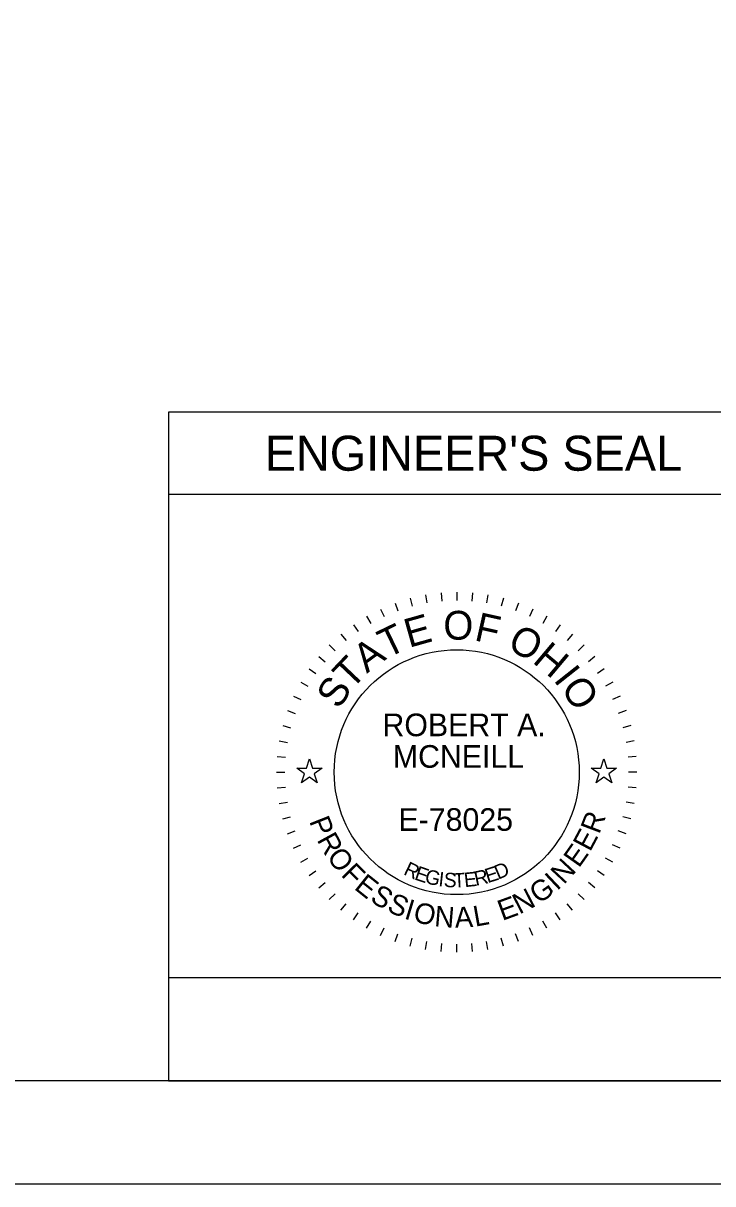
# Model space of a CAD drawing. Extents: x 0 to 34, y 0 to 22.
# Drawn here: x 6.64 to 9.99, y 0 to 5.64 of the extents above; entities that cross this region are included whole.
import ezdxf

# ---------------------------------------------------------------- set-up
doc = ezdxf.new("R2010")
doc.units = 0
for name, color, linetype in [('Default', 7, 'Continuous'), ('SH_Border', 7, 'Continuous'), ('SH_Cut_Line', 7, 'Continuous'), ('SH_Data', 7, 'Continuous')]:
    doc.layers.add(name, color=color, linetype=linetype)

msp = doc.modelspace()

# ---------------------------------------------------------------- linework, layer by layer
at = {"layer": 'Default'}
for points in [[(7.9736, 2.02), (8.0205, 2.02), (8.035, 2.0645), (8.0495, 2.02), (8.0964, 2.02), (8.0585, 1.9924), (8.073, 1.9478), (8.035, 1.9754), (7.997, 1.9478), (8.0115, 1.9924)], [(9.4036, 2.02), (9.4505, 2.02), (9.465, 2.0645), (9.4795, 2.02), (9.5264, 2.02), (9.4885, 1.9924), (9.503, 1.9478), (9.465, 1.9754), (9.427, 1.9478), (9.4415, 1.9924)]]:
    msp.add_lwpolyline(points, close=True, dxfattribs=at)
at = {"layer": 'SH_Border'}
msp.add_lwpolyline([(1.5, 21.5), (33.5, 21.5), (33.5, 0.5), (1.5, 0.5)], close=True, dxfattribs=at)
at = {"layer": 'SH_Cut_Line'}
msp.add_lwpolyline([(0, 0), (34, 0), (34, 22), (0, 22)], close=True, dxfattribs=at)
at = {"layer": 'SH_Data'}
for p, q in [((10.15, 3.75), (7.35, 3.75)), ((7.35, 3.75), (7.35, 0.5)), ((10.15, 3.35), (7.35, 3.35)), ((8.4507, 2.8222), (8.4644, 2.7846)), ((8.5235, 2.8452), (8.5339, 2.8065)), ((8.5981, 2.8617), (8.605, 2.8223)), ((8.6737, 2.8717), (8.6772, 2.8318)), ((8.75, 2.875), (8.75, 2.835)), ((8.8263, 2.8717), (8.8228, 2.8318)), ((8.9019, 2.8617), (8.895, 2.8223)), ((8.9765, 2.8452), (8.9661, 2.8065)), ((9.0493, 2.8222), (9.0356, 2.7846)), ((8.3802, 2.793), (8.3971, 2.7568)), ((9.1198, 2.793), (9.1029, 2.7568)), ((8.2481, 2.7168), (8.2711, 2.684)), ((8.3125, 2.7578), (8.3325, 2.7231)), ((9.1875, 2.7578), (9.1675, 2.7231)), ((9.2519, 2.7168), (9.2289, 2.684)), ((8.1876, 2.6703), (8.2133, 2.6396)), ((9.3124, 2.6703), (9.2867, 2.6396)), ((8.1313, 2.6187), (8.1596, 2.5904)), ((9.3687, 2.6187), (9.3404, 2.5904)), ((8.0797, 2.5624), (8.1104, 2.5367)), ((9.4203, 2.5624), (9.3896, 2.5367)), ((8.0332, 2.5019), (8.066, 2.4789)), ((9.4668, 2.5019), (9.434, 2.4789)), ((7.9922, 2.4375), (8.0269, 2.4175)), ((9.5078, 2.4375), (9.4731, 2.4175)), ((7.957, 2.3698), (7.9932, 2.3529)), ((9.543, 2.3698), (9.5068, 2.3529)), ((7.9278, 2.2993), (7.9654, 2.2856)), ((9.5722, 2.2993), (9.5346, 2.2856)), ((7.9048, 2.2265), (7.9435, 2.2161)), ((9.5952, 2.2265), (9.5565, 2.2161)), ((7.8883, 2.1519), (7.9277, 2.145)), ((9.6117, 2.1519), (9.5723, 2.145)), ((7.8783, 2.0763), (7.9182, 2.0728)), ((9.6217, 2.0763), (9.5818, 2.0728)), ((7.875, 2), (7.915, 2)), ((9.625, 2), (9.585, 2)), ((7.8783, 1.9237), (7.9182, 1.9272)), ((9.6217, 1.9237), (9.5818, 1.9272)), ((7.8883, 1.8481), (7.9277, 1.855)), ((9.6117, 1.8481), (9.5723, 1.855)), ((7.9048, 1.7735), (7.9435, 1.7839)), ((9.5952, 1.7735), (9.5565, 1.7839)), ((7.9278, 1.7007), (7.9654, 1.7144)), ((9.5722, 1.7007), (9.5346, 1.7144)), ((7.957, 1.6302), (7.9932, 1.6471)), ((9.543, 1.6302), (9.5068, 1.6471)), ((7.9922, 1.5625), (8.0269, 1.5825)), ((9.5078, 1.5625), (9.4731, 1.5825)), ((8.0332, 1.4981), (8.066, 1.5211)), ((9.4668, 1.4981), (9.434, 1.5211)), ((8.0797, 1.4376), (8.1104, 1.4633)), ((9.4203, 1.4376), (9.3896, 1.4633)), ((8.1313, 1.3813), (8.1596, 1.4096)), ((8.1876, 1.3297), (8.2133, 1.3604)), ((9.3124, 1.3297), (9.2867, 1.3604)), ((9.3687, 1.3813), (9.3404, 1.4096)), ((8.2481, 1.2832), (8.2711, 1.316)), ((9.2519, 1.2832), (9.2289, 1.316)), ((8.3125, 1.2422), (8.3325, 1.2769)), ((8.3802, 1.207), (8.3971, 1.2432)), ((9.1198, 1.207), (9.1029, 1.2432)), ((9.1875, 1.2422), (9.1675, 1.2769)), ((8.4507, 1.1778), (8.4644, 1.2154)), ((8.5235, 1.1548), (8.5339, 1.1935)), ((8.9765, 1.1548), (8.9661, 1.1935)), ((9.0493, 1.1778), (9.0356, 1.2154)), ((8.5981, 1.1383), (8.605, 1.1777)), ((8.6737, 1.1283), (8.6772, 1.1682)), ((8.75, 1.125), (8.75, 1.165)), ((8.8263, 1.1283), (8.8228, 1.1682)), ((8.9019, 1.1383), (8.895, 1.1777)), ((10.15, 0.5), (7.35, 0.5))]:
    msp.add_line(p, q, dxfattribs=at)
msp.add_lwpolyline([(10.15, 0.5), (10.15, 1), (7.35, 1), (7.35, 0.5)], close=True, dxfattribs=at)
msp.add_circle((8.75, 2), 0.595, dxfattribs=at)

# ---------------------------------------------------------------- texts
for s, height, p in [("ENGINEER'S SEAL", 0.17, (7.8176, 3.465)), ('ROBERT A.', 0.11, (8.3895, 2.1749)), ('MCNEILL', 0.11, (8.4398, 2.0216)), ('E-78025', 0.11, (8.4673, 1.7151))]:
    msp.add_text(s, height=height, dxfattribs=at).set_placement(p)
for s, height, rotation, p in [('E', 0.14, 15.7571, (8.5184, 2.6038)), ('O', 0.14, 359.7812, (8.6847, 2.6443)), ('F', 0.14, 347.4362, (8.8311, 2.6417)), ('T', 0.14, 25.7167, (8.4116, 2.5518)), ('O', 0.14, 332.2586, (8.9898, 2.6015)), ('A', 0.14, 36.4747, (8.3134, 2.4781)), ('H', 0.14, 319.9136, (9.1132, 2.5361)), ('T', 0.14, 46.4344, (8.2383, 2.3964)), ('I', 0.14, 308.367, (9.2165, 2.4483)), ('S', 0.14, 57.1924, (8.1781, 2.3014)), ('O', 0.14, 303.1491, (9.2521, 2.4089)), ('R', 0.1, 69.2322, (9.4419, 1.6954)), ('P', 0.1, 291.494, (8.0323, 1.7621)), ('R', 0.1, 298.7311, (8.069, 1.6717)), ('E', 0.1, 61.9951, (9.3976, 1.6098)), ('E', 0.1, 54.758, (9.3433, 1.5314)), ('O', 0.1, 306.4666, (8.1155, 1.5883)), ('N', 0.1, 47.0224, (9.2702, 1.4508)), ('F', 0.1, 314.7068, (8.1843, 1.4983)), ('R', 0.07, 334.487, (8.4875, 1.5051)), ('E', 0.07, 341.04, (8.5406, 1.4801)), ('G', 0.07, 347.4752, (8.5914, 1.4618)), ('R', 0.07, 11.9184, (8.8425, 1.4474)), ('E', 0.07, 17.6836, (8.8998, 1.4602)), ('D', 0.07, 23.3052, (8.951, 1.477)), ('E', 0.1, 321.4393, (8.2478, 1.4348)), ('I', 0.07, 353.7858, (8.6591, 1.4468)), ('S', 0.07, 356.8926, (8.6858, 1.4429)), ('T', 0.07, 3.0061, (8.7357, 1.4387)), ('E', 0.07, 6.0117, (8.7889, 1.4412)), ('G', 0.1, 35.0469, (9.1481, 1.357)), ('I', 0.1, 43.287, (9.2368, 1.4214)), ('S', 0.1, 328.6764, (8.3243, 1.3752)), ('N', 0.1, 27.3113, (9.0545, 1.3075)), ('S', 0.1, 335.9134, (8.4064, 1.3266)), ('I', 0.1, 343.1505, (8.4906, 1.2897)), ('O', 0.1, 346.8859, (8.5339, 1.2751)), ('E', 0.1, 20.0742, (8.9712, 1.277)), ('N', 0.1, 355.1261, (8.6388, 1.2517)), ('A', 0.1, 2.8617, (8.7423, 1.2437)), ('L', 0.1, 10.0987, (8.8394, 1.249))]:
    msp.add_text(s, height=height, rotation=rotation, dxfattribs=at).set_placement(p)

doc.saveas('drawing.dxf')
